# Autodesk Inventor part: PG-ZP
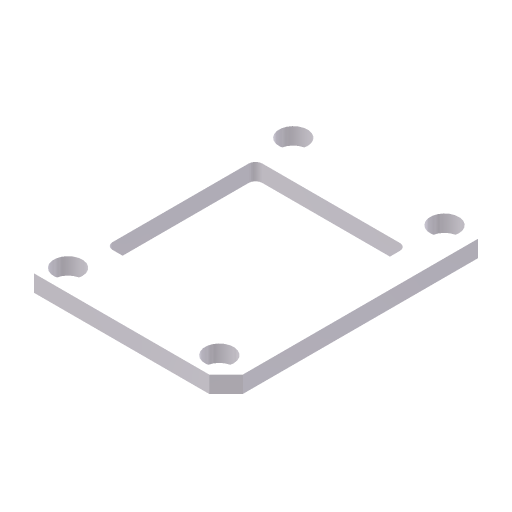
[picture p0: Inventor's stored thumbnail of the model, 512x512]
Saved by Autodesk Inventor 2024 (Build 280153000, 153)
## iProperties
Company: ATC
Shininess: 20.0
Length Units: 11269
Angle Units: 11279
Time Units: 11290
Mass Units: 11283
Length Display Precision: 3
Angle Display Precision: 2
Compacted: True
Created: 2023-03
Part Number: PG-ZP
Document SubType Name: Modeling
Designer: Andrzej Jaskulski
Density: 1 g/cm^3
Material: Kurs-AJ
Appearance: Kurs-AJ
Checked By: A.J.
Engr Approved By: Andrzej Jaskulski
Mfg Approved By: Andrzej Jaskulski
Authority: A.J.
Density: 0.0
Volumn: 0.0
Area: 0.0
PropertySet Name: Model Information
Control State: 0
Master: False
Checked Out: False
Title: A.J.: Kurs R2024-MEP
Author: Andrzej Jaskulski
Revision Number: 1/24
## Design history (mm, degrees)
sketch "Sketch1"
  geometry: L1 (37.5, -40)-(-24.672, -40) reference; L2 (-24.672, 40)-(37.5, 40) reference; L3 (37.5, -40)-(-24.672, -40); L4 (-24.672, -40)-(-24.672, 40); L5 (-24.672, 40)-(37.5, 40); L6 (37.5, 40)-(37.5, -40); L7 (37.5, -22.264)-(-32.672, -22.264) reference; L8 (-32.672, 22.264)-(37.5, 22.264) reference; L9 (27, -22.264)-(-14, -22.264); L10 (-16, -20.264)-(-16, 20.264); L11 (-14, 22.264)-(27, 22.264); L12 (29, 20.264)-(29, -20.264); C1 r 3.32 at (29, 33.5) reference; C2 r 3.32 at (29, -33.5) reference; C3 r 3.32 at (-16, -33.5) reference; C4 r 3.32 at (-16, 33.5) reference; C5 r 4.25 at (29, -33.5); C6 r 4.25 at (-16, -33.5); C7 r 4.25 at (29, 33.5); C8 r 4.25 at (-16, 33.5); A1 r 2 centre (27, -20.264) between (27, -22.264) and (29, -20.264); A2 r 2 centre (-14, -20.264) between (-16, -20.264) and (-14, -22.264); A3 r 2 centre (-14, 20.264) between (-14, 22.264) and (-16, 20.264); A4 r 2 centre (27, 20.264) between (29, 20.264) and (27, 22.264); 2 further points
  constraints: 16 end point, 8 centre point, 8 point on circle, 8 tangent, 6 point on line, 4 coincident, 4 parallel, 3 equal radius, 2 horizontal, 2 perpendicular
  dimensions: "d0" = 8.5 diameter of C5; "d1" = 8.5 diameter of C6 (= d0); "d2" = 8.5 diameter of C7 (= d0); "d3" = 8.5 diameter of C8 (= d0); "d4" = 2 radius of A1
extrude "Extrusion1" new body sketch "Sketch1" distance "d5" = 5; taper "d6" = 0 deg
chamfer "Chamfer1" distance "d7" = 5; stored, may be unused: second distance "d8" = 5, angle "d9" = 45 deg
node "Bryła1"
node "Korpusy bryłowe"
node "Korpusy powierzchniowe"
